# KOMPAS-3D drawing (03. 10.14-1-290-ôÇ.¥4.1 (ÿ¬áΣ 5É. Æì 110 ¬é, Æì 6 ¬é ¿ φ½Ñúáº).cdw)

Views: Вид 1
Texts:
  Текст на чертеже
  Размерные надписи
  Шероховатость
  Линия-выноска #1
  Линия-выноска #2
  Линия-выноска #3
  Отклонения формы и база
  Заголовок таблицы
  Ячейка таблицы
  Стрелка вида
  Обозначение изменения
  Фигурная скобка
  Номер узла
  Марка координационной оси
  VRCB
  Выносная надпись
  Обозначение узла
  Марка/позиционное обозначение с линией-выноской
  Марка/позиционное обозначение на линии
  Марка/позиционное обозначение без линии-выноски
  Аппараты
  маркировка
  Маркировка
  Левая боковина
  TV1G
  Цепи напряжения
  Условно-графические обозначения:
  Колодка маркировочная
  Клемма измерительная
  Мостик контактный
  Концевая пластина/разделитель
  Клемма проходная
  Правая боковина
  TV1Р
  TV2Р
  Цепи сигнализации
  +EH
  + EH
  (+)ЕР
  Цепи освещения
  -EH
  ЕНА
  ЕНР
  Элегаз
  KL1:A
  KL2:A
  KL3:A
  KL4:A
  KL5:A
  KL6:A
  Цепи питания
  +ЕС1.1
  -ЕС1.1
  +ЕС1.2
  -ЕС1.2
  SF4:C1
  SF5:C1
  SF14:C1
  SF15:C1
  Реконструкция ПС 110 кВ Опорная
  (замена трансформаторов 16МВА на 40МВА)
  11.09/125.003-290-ЭП.Э4.04-
  Н.контр.
  Шкаф 5Р. ТН 110 кВ, ТН 6 кВ и элегаз.
  Схема рядов зажимов
  Борисов
  Разраб.
  Алдошина
  Схема электрическая соединений
Dimensions and other numbers on the sheet: 10/14-1-290-УА.Э4.1; 7; 3,2 (надписи); 2,5 (контакты, клеммы); 01; 1; 2; 3; 4; 5; 6; 8; 9; 10; 11; 12; 13; 14; 15; 16; 17; 18; 19; 20; 21; 22; 23; 24; 25; 26; 27; 28; 29; 30; 31; 32; 33; 34; 35; 36; 37; 38; 39; 40; 02; 41; 42; 43; 44; 45; 46; 47; 48; 49; 50; 51; 52; 53; 54; 55; 56; 57; 58; 59; 60; 00; 03; 04; 61; 62; 63; 64; 65; 66; 67; 68; 69; 70; 71; 72; 73; 74; 75; 76; 77; 78; 79; 80; 11.12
